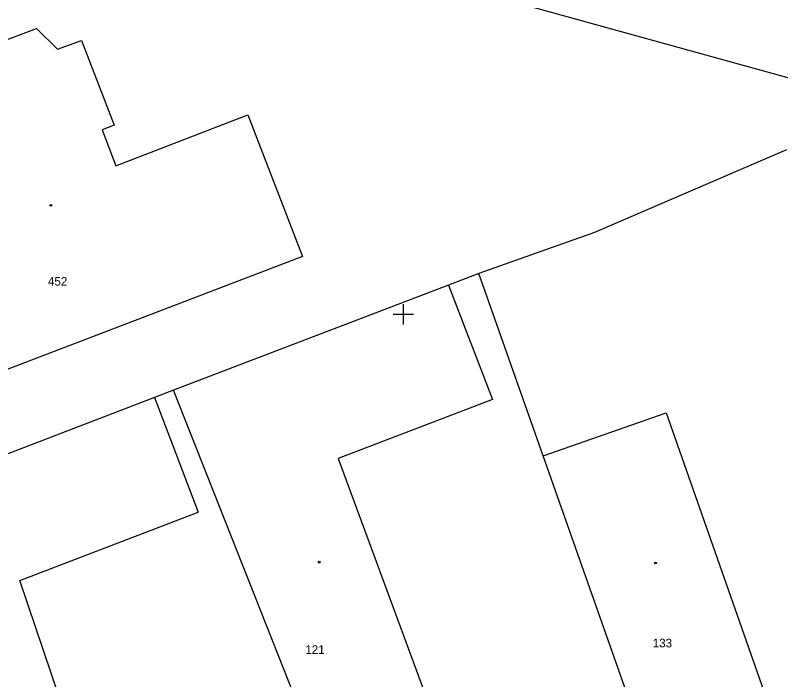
# Model space of a CAD drawing. Extents: x -703403 to -701924, y -1022520 to -1021856.
# Drawn here: x -703093.98 to -703056.54, y -1022017.88 to -1021985.37 of the extents above; entities that cross this region are included whole.
import ezdxf

# ---------------------------------------------------------------- set-up
doc = ezdxf.new("R2010")
doc.units = 0
for name, color, linetype in [('Z_hektometricka_sit', 7, 'Continuous'), ('Z_katastr_cisla_stavebni', 7, 'Continuous'), ('Z_katastr_hranice', 7, 'Continuous'), ('Z_katastr_vnitrni_kresba', 7, 'Continuous'), ('Z_katastr_znacky_budov', 7, 'Continuous')]:
    doc.layers.add(name, color=color, linetype=linetype)

msp = doc.modelspace()

# ---------------------------------------------------------------- linework, layer by layer
at = {"layer": 'Z_hektometricka_sit'}
for p, q in [((-703075, -1021999.5), (-703075, -1022000.5)), ((-703075.5, -1022000), (-703074.5, -1022000))]:
    msp.add_line(p, q, dxfattribs=at)
at = {"layer": 'Z_katastr_hranice'}
for p, q in [((-703051.25, -1021989.8), (-703095.03, -1021977.67)), ((-703094.96, -1021986.77), (-703092.95, -1021986.01)), ((-703092.95, -1021986.01), (-703091.92, -1021987.03)), ((-703091.92, -1021987.03), (-703090.74, -1021986.61)), ((-703090.74, -1021986.61), (-703089.14, -1021990.75)), ((-703089.07, -1021992.74), (-703082.61, -1021990.24)), ((-703082.61, -1021990.24), (-703079.94, -1021997.17)), ((-703089.14, -1021990.75), (-703089.74, -1021990.98)), ((-703089.74, -1021990.98), (-703089.07, -1021992.74)), ((-703056.26, -1021991.96), (-703065.64, -1021996)), ((-703065.64, -1021996), (-703071.3, -1021998)), ((-703079.94, -1021997.17), (-703100.1, -1022004.89)), ((-703071.3, -1021998), (-703072.79, -1021998.57)), ((-703068.15, -1022006.93), (-703071.3, -1021998)), ((-703072.79, -1021998.57), (-703086.24, -1022003.72)), ((-703086.24, -1022003.72), (-703087.18, -1022004.08)), ((-703076.75, -1022027.74), (-703086.24, -1022003.72)), ((-703087.18, -1022004.08), (-703101.56, -1022009.59)), ((-703062.66, -1022022.49), (-703068.15, -1022006.93))]:
    msp.add_line(p, q, dxfattribs=at)
at = {"layer": 'Z_katastr_vnitrni_kresba'}
for p, q in [((-703072.79, -1021998.57), (-703070.64, -1022004.17)), ((-703087.18, -1022004.08), (-703085.03, -1022009.68)), ((-703070.64, -1022004.17), (-703078.18, -1022007.06)), ((-703068.15, -1022006.93), (-703062.14, -1022004.82)), ((-703062.14, -1022004.82), (-703056.68, -1022020.39)), ((-703078.18, -1022007.06), (-703071.29, -1022025.78)), ((-703093.76, -1022013.03), (-703085.03, -1022009.68)), ((-703087.46, -1022031.63), (-703093.76, -1022013.03))]:
    msp.add_line(p, q, dxfattribs=at)
at = {"layer": 'Z_katastr_znacky_budov'}
for centre in [(-703092.242, -1021994.67), (-703079.112, -1022012.13), (-703062.662, -1022012.17)]:
    msp.add_circle(centre, 0.0437, dxfattribs=at)

# ---------------------------------------------------------------- texts
at = {"layer": 'Z_katastr_cisla_stavebni'}
for s, p in [('452', (-703092.388, -1021998.6)), ('133', (-703062.799, -1022016.299)), ('121', (-703079.795, -1022016.62))]:
    msp.add_text(s, height=0.425, dxfattribs=at).set_placement(p)

doc.saveas('drawing.dxf')
